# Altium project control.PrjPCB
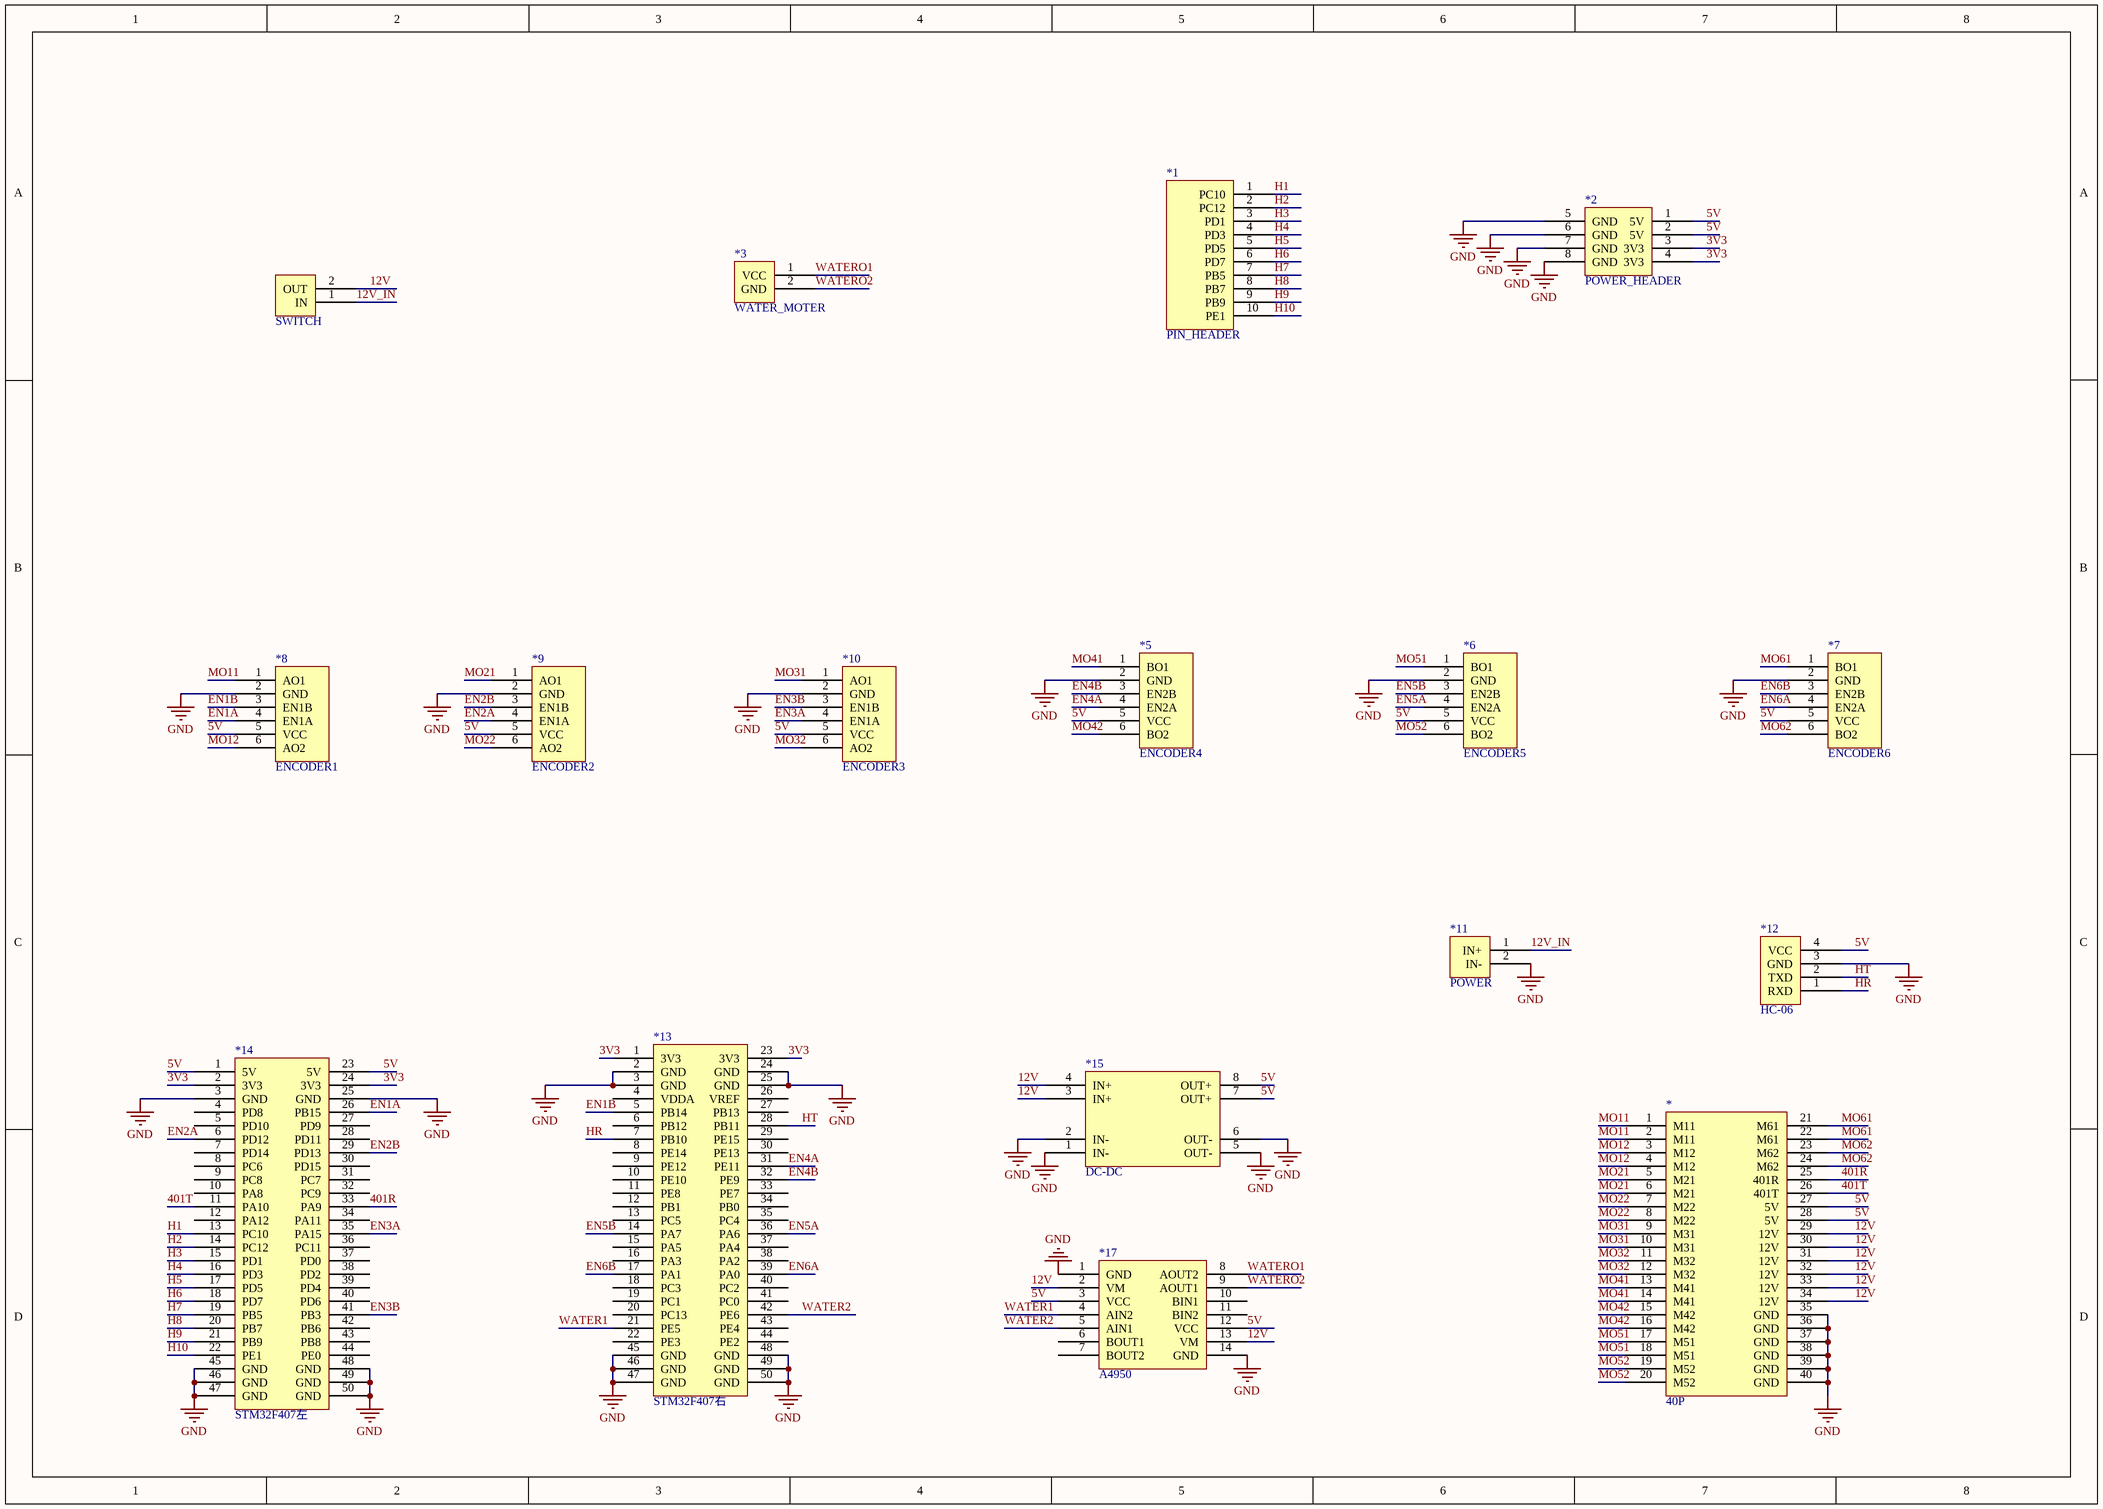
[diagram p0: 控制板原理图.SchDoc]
1 sheet, 17 parts. Net scope: global (net labels, ports and power ports of the same name join across sheets).
Board file: 控制板PCB.PcbDoc

## Sheet 控制板原理图.SchDoc
size A3

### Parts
*  40P  [PCBComponent_1]
*1  PIN_HEADER  [PIN_HEADER]
*2  POWER_HEADER  [POWER_HEADER]
*3  WATER_MOTER  [WATER_HEADER]
*5  ENCODER4  [ENCODER2]
*6  ENCODER5  [ENCODER2]
*7  ENCODER6  [ENCODER2]
*8  ENCODER1  [ENCODER1]
*9  ENCODER2  [ENCODER1]
*10  ENCODER3  [ENCODER1]
*11  POWER  [POWER]
*12  HC-06  [HC-06]
*13  STM32F407右  [STM32F407左]
*14  STM32F407左  [STM32F407左]
*15  DC-DC  [DC-DC]
*17  A4950  [A4950]
  SWITCH  [switch]

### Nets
GND: *.35(GND) *.36(GND) *.37(GND) *.38(GND) *.39(GND) *.40(GND) *2.5(GND) *2.6(GND) *2.7(GND) *2.8(GND) *5.2(GND) *6.2(GND) *7.2(GND) *8.2(GND) *9.2(GND) *10.2(GND) *11.2(IN-) *12.3(GND) *13.2(GND) *13.3(GND) *13.24(GND) *13.25(GND) *13.45(GND) *13.46(GND) *13.47(GND) *13.48(GND) *13.49(GND) *13.50(GND) *14.3(GND) *14.25(GND) *14.45(GND) *14.46(GND) *14.47(GND) *14.48(GND) *14.49(GND) *14.50(GND) *15.1(IN-) *15.2(IN-) *15.5(OUT-) *15.6(OUT-) *17.1(GND) *17.14(GND)
3V3: *2.3(3V3) *2.4(3V3) *13.1(3V3) *13.23(3V3) *14.2(3V3) *14.24(3V3)
5V: *.27(5V) *.28(5V) *2.1(5V) *2.2(5V) *5.5(VCC) *6.5(VCC) *7.5(VCC) *8.5(VCC) *9.5(VCC) *10.5(VCC) *12.4(VCC) *14.1(5V) *14.23(5V) *15.7(OUT+) *15.8(OUT+) *17.3(VCC) *17.12(VCC)
12V: *.29(12V) *.30(12V) *.31(12V) *.32(12V) *.33(12V) *.34(12V) *15.3(IN+) *15.4(IN+) *17.2(VM) *17.13(VM) .2(OUT)
12V_IN: *11.1(IN+) .1(IN)
401R: *.25(401R) *14.33(PA9)
401T: *.26(401T) *14.11(PA10)
EN1A: *8.4(EN1A) *14.26(PB15)
EN1B: *8.3(EN1B) *13.5(PB14)
EN2A: *9.4(EN1A) *14.6(PD12)
EN2B: *9.3(EN1B) *14.29(PD13)
EN3A: *10.4(EN1A) *14.35(PA15)
EN3B: *10.3(EN1B) *14.41(PB3)
EN4A: *5.4(EN2A) *13.31(PE11)
EN4B: *5.3(EN2B) *13.32(PE9)
EN5A: *6.4(EN2A) *13.36(PA6)
EN5B: *6.3(EN2B) *13.14(PA7)
EN6A: *7.4(EN2A) *13.39(PA0)
EN6B: *7.3(EN2B) *13.17(PA1)
H1: *1.1(PC10) *14.13(PC10)
H2: *1.2(PC12) *14.14(PC12)
H3: *1.3(PD1) *14.15(PD1)
H4: *1.4(PD3) *14.16(PD3)
H5: *1.5(PD5) *14.17(PD5)
H6: *1.6(PD7) *14.18(PD7)
H7: *1.7(PB5) *14.19(PB5)
H8: *1.8(PB7) *14.20(PB7)
H9: *1.9(PB9) *14.21(PB9)
H10: *1.10(PE1) *14.22(PE1)
HR: *12.1(RXD) *13.7(PB10)
HT: *12.2(TXD) *13.28(PB11)
MO11: *.1(M11) *.2(M11) *8.1(AO1)
MO12: *.3(M12) *.4(M12) *8.6(AO2)
MO21: *.5(M21) *.6(M21) *9.1(AO1)
MO22: *.7(M22) *.8(M22) *9.6(AO2)
MO31: *.9(M31) *.10(M31) *10.1(AO1)
MO32: *.11(M32) *.12(M32) *10.6(AO2)
MO41: *.13(M41) *.14(M41) *5.1(BO1)
MO42: *.15(M42) *.16(M42) *5.6(BO2)
MO51: *.17(M51) *.18(M51) *6.1(BO1)
MO52: *.19(M52) *.20(M52) *6.6(BO2)
MO61: *.21(M61) *.22(M61) *7.1(BO1)
MO62: *.23(M62) *.24(M62) *7.6(BO2)
WATER1: *13.21(PE5) *17.4(AIN2)
WATER2: *13.42(PE6) *17.5(AIN1)
WATERO1: *3.1(VCC) *17.8(AOUT2)
WATERO2: *3.2(GND) *17.9(AOUT1)

Not connected (* = marked no-connect by the designer): *13 4(VDDA) 6(PB12) 8(PE14) 9(PE12) 10(PE10) 11(PE8) 12(PB1) 13(PC5) 15(PA5) 16(PA3) 18(PC3) 19(PC1) 20(PC13) 22(PE3) 26(VREF) 27(PB13) 29(PE15) 30(PE13) 33(PE7) 34(PB0) 35(PC4) 37(PA4) 38(PA2) 40(PC2) 41(PC0) 43(PE4) 44(PE2); *14 4(PD8) 5(PD10) 7(PD14) 8(PC6) 9(PC8) 10(PA8) 12(PA12) 27(PD9) 28(PD11) 30(PD15) 31(PC7) 32(PC9) 34(PA11) 36(PC11) 37(PD0) 38(PD2) 39(PD4) 40(PD6) 42(PB6) 43(PB8) 44(PE0); *17 6(BOUT1) 7(BOUT2) 10(BIN1) 11(BIN2)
